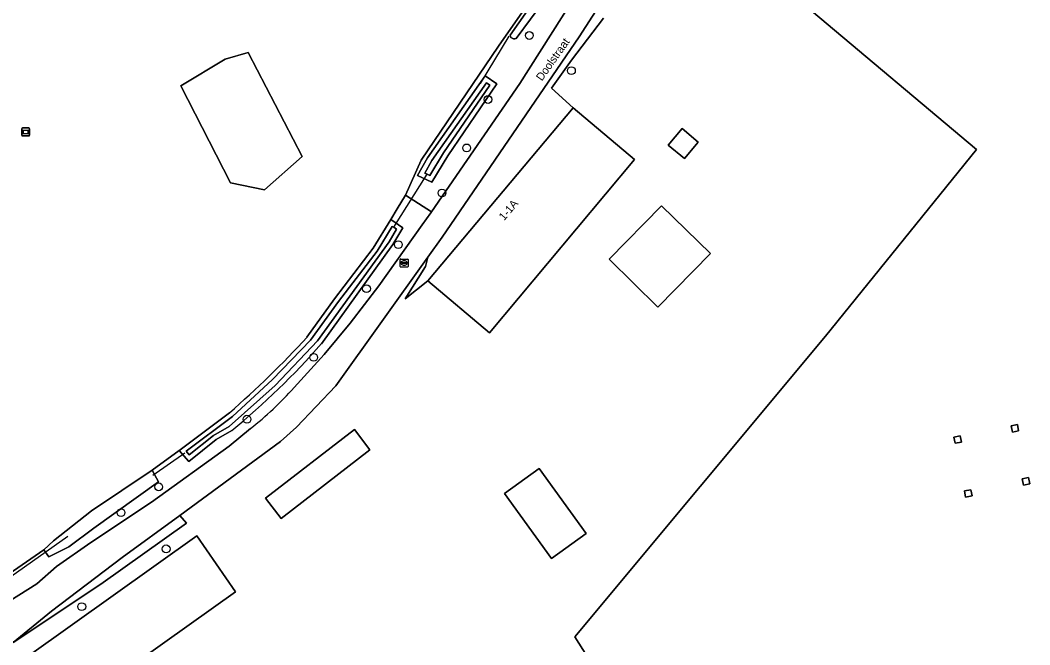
# Model space of a CAD drawing. Extents: x 164494 to 166241, y 382475 to 384495.
# Drawn here: x 165148.9 to 165275, y 383054.9 to 383132.9 of the extents above; entities that cross this region are included whole.
import ezdxf

# ---------------------------------------------------------------- set-up
doc = ezdxf.new("R2010")
doc.units = 0
for name, color, linetype in [('IMGEO_Boom', 7, 'Continuous'), ('IMGEO_Bouwland', 7, 'Continuous'), ('IMGEO_Duiker', 7, 'Continuous'), ('IMGEO_Erf', 7, 'Continuous'), ('IMGEO_Grasland_overig', 7, 'Continuous'), ('IMGEO_Groenvoorziening', 7, 'Continuous'), ('IMGEO_Hek', 7, 'Continuous'), ('IMGEO_Hoogspanningsmast', 7, 'Continuous'), ('IMGEO_Loofbos', 7, 'Continuous'), ('IMGEO_Oever', 7, 'Continuous'), ('IMGEO_Openbare_ruimte_label', 7, 'Continuous'), ('IMGEO_Pand', 7, 'Continuous'), ('IMGEO_Pand_nummerreeks', 7, 'Continuous'), ('IMGEO_Rijbaan_lokaal_halfverhard', 7, 'Continuous'), ('IMGEO_Rioolput', 7, 'Continuous'), ('IMGEO_Verklikker', 7, 'Continuous'), ('IMGEO_Waterloop', 7, 'Continuous')]:
    doc.layers.add(name, color=color, linetype=linetype)

msp = doc.modelspace()

# ---------------------------------------------------------------- linework, layer by layer
at = {"layer": 'IMGEO_Boom'}
for centre in [(165212.48, 383130.99), (165217.73, 383126.59), (165207.31, 383122.99), (165204.64, 383116.94), (165201.56, 383111.31), (165196.1, 383104.86), (165192.13, 383099.35), (165185.53, 383090.77), (165177.19, 383083.04), (165166.16, 383074.59), (165161.46, 383071.37), (165167.09, 383066.84), (165156.55, 383059.63)]:
    msp.add_circle(centre, 0.489, dxfattribs=at)
at = {"layer": 'IMGEO_Bouwland'}
for points in [[(165074.12, 383155.42), (165090.98, 383126.27), (165109.32, 383102.17), (165116.19, 383099.11), (165122.51, 383097.15), (165123.71, 383095.2), (165123.72, 383093.89), (165120.24, 383087.21), (165137.05, 383064.06), (165140.6, 383063.91), (165142.91, 383065.45), (165147.5, 383063.74), (165151.82, 383066.74), (165153, 383067.83), (165157.78, 383071.58), (165165.33, 383076.66), (165168.73, 383079.13), (165168.86, 383079.22), (165175, 383083.84)], [(165184.69, 383093.31), (165188.14, 383098.1), (165192.97, 383104.4), (165195.15, 383107.98), (165195.96, 383109.31), (165197, 383111.02), (165198.96, 383115.4), (165208.62, 383129.64), (165221.63, 383148.27)], [(165247.72, 383134.08), (165268.36, 383116.74), (165249.48, 383093.43), (165218.15, 383055.85), (165223.66, 383047.14)]]:
    msp.add_lwpolyline(points, dxfattribs=at)
for points in [[(165177.36, 383128.85), (165184.08, 383115.87), (165179.39, 383111.69), (165175.14, 383112.58), (165168.94, 383124.68), (165174.45, 383128.05)], [(165273.45, 383082.38), (165273.6, 383081.59), (165272.83, 383081.42), (165272.68, 383082.22)], [(165266.31, 383080.98), (165266.46, 383080.19), (165265.68, 383080.04), (165265.52, 383080.82)], [(165274.84, 383075.77), (165275.01, 383074.98), (165274.22, 383074.82), (165274.06, 383075.6)], [(165267.62, 383074.24), (165267.79, 383073.47), (165266.99, 383073.31), (165266.83, 383074.08)]]:
    msp.add_lwpolyline(points, close=True, dxfattribs=at)
msp.add_arc((165091.58, 383178.94), 126.51, 311.2584, 317.3955, dxfattribs=at)
at = {"layer": 'IMGEO_Duiker'}
for points in [[(165209.93, 383130.92), (165206.34, 383125)], [(165195.55, 383107.03), (165199.72, 383113.65)], [(165165.42, 383076.05), (165169.45, 383078.84)], [(165147.67, 383063.4), (165154.79, 383068.45)]]:
    msp.add_lwpolyline(points, dxfattribs=at)
at = {"layer": 'IMGEO_Erf'}
for points in [[(165147.19, 383054.58), (165154.26, 383044.06), (165156.24, 383041.34), (165158.94, 383038.39), (165159.48, 383037.85), (165160.12, 383037.5), (165161.03, 383037.44), (165161.58, 383037.57), (165162.78, 383037.82), (165169.28, 383031.59), (165170.09, 383032.35), (165171.96, 383030.47), (165176.32, 383026.1), (165185, 383018.32), (165194.85, 383024.31), (165208.27, 383034.25), (165223.66, 383047.14), (165218.15, 383055.85), (165249.48, 383093.43), (165268.36, 383116.74), (165247.72, 383134.08)], [(165221.76, 383133.17), (165217.74, 383127.91), (165215.23, 383124.42), (165217.94, 383121.93), (165225.63, 383115.48), (165207.5, 383093.85), (165199.79, 383100.32), (165196.97, 383098.1), (165199.49, 383102.14), (165199.81, 383103.29), (165188.28, 383087.23), (165183.37, 383082.04), (165181.4, 383080.25), (165168.79, 383071.02), (165169.63, 383070.04), (165158.92, 383062.43), (165147.97, 383055.13)]]:
    msp.add_lwpolyline(points, dxfattribs=at)
for points in [[(165229.84, 383117.3), (165231.57, 383119.36), (165233.58, 383117.67), (165231.86, 383115.61)], [(165222.44, 383103.02), (165229, 383109.72), (165235.09, 383103.76), (165228.53, 383097.06)], [(165192.55, 383079.23), (165181.45, 383070.63), (165179.49, 383073.16), (165190.61, 383081.75)], [(165213.7, 383076.89), (165219.57, 383068.78), (165215.23, 383065.65), (165209.36, 383073.75)], [(165175.75, 383061.48), (165157.81, 383048.67), (165156.81, 383050.14), (165153.69, 383047.91), (165150.01, 383053.56), (165170.91, 383068.49)]]:
    msp.add_lwpolyline(points, close=True, dxfattribs=at)
at = {"layer": 'IMGEO_Grasland_overig'}
for points in [[(165226.93, 383152.39), (165210.82, 383130.6), (165210.68, 383130.59), (165210.5, 383130.59), (165210.4, 383130.6), (165210.24, 383130.69), (165210.18, 383130.75), (165210.13, 383130.88), (165210.09, 383131.01), (165218.46, 383142.98)], [(165221.63, 383148.27), (165208.62, 383129.64), (165198.96, 383115.4), (165197, 383111.02), (165200.23, 383108.95), (165211.27, 383124.97), (165221.98, 383141.91)], [(165226.21, 383142.5), (165218.7, 383130.81), (165201.6, 383105.79), (165199.81, 383103.29), (165199.49, 383102.14), (165196.97, 383098.1), (165199.79, 383100.32), (165217.94, 383121.93), (165215.23, 383124.42), (165217.74, 383127.91), (165221.76, 383133.17)], [(165175.31, 383081.64), (165173.36, 383080.5), (165169.91, 383077.78), (165168.73, 383079.13), (165165.33, 383076.66), (165166.13, 383075.22), (165158.05, 383069.44), (165154.94, 383067.08), (165152.43, 383065.87), (165151.82, 383066.74), (165147.5, 383063.74), (165142.91, 383065.45), (165140.6, 383063.91), (165137.05, 383064.06), (165120.24, 383087.21), (165123.72, 383093.89), (165123.71, 383095.2), (165122.51, 383097.15), (165116.19, 383099.11), (165109.32, 383102.17), (165090.98, 383126.27)], [(165183.08, 383087), (165186.84, 383091.11), (165190.1, 383095.04), (165193.65, 383099.72), (165199.07, 383107.32), (165200.16, 383108.84), (165200.23, 383108.95), (165197, 383111.02), (165195.96, 383109.31), (165195.15, 383107.98), (165196.66, 383106.95), (165195.43, 383104.86), (165186.49, 383092.48)], [(165138.95, 383055.65), (165138.65, 383055.4), (165139.68, 383055.19), (165145.27, 383058.94), (165150.95, 383062.46), (165153.38, 383064.63), (165157.7, 383067.66), (165165.26, 383072.66), (165174.96, 383079.68), (165177.63, 383081.87)]]:
    msp.add_lwpolyline(points, dxfattribs=at)
msp.add_lwpolyline([(165206.95, 383125.96), (165208.43, 383124.96), (165202.29, 383115.96), (165200.29, 383112.66), (165198.52, 383113.49), (165199.74, 383115.69)], close=True, dxfattribs=at)
for centre, radius, start, end in [((165116.7, 383153.32), 92.59, 309.2748, 318.9253), ((165151.38, 383115.19), 42.42, 308.2249, 318.3405)]:
    msp.add_arc(centre, radius, start, end, dxfattribs=at)
at = {"layer": 'IMGEO_Groenvoorziening'}
msp.add_lwpolyline([(165152.79, 383059.07), (165147.97, 383055.13), (165158.92, 383062.43), (165169.63, 383070.04), (165168.79, 383071.02), (165161.61, 383065.76)], close=True, dxfattribs=at)
at = {"layer": 'IMGEO_Hek'}
msp.add_lwpolyline([(165249.48, 383093.43), (165268.36, 383116.74), (165248.56, 383133.37)], dxfattribs=at)
at = {"layer": 'IMGEO_Hoogspanningsmast'}
for points in [[(165273.6, 383081.59), (165273.45, 383082.38), (165272.68, 383082.22), (165272.83, 383081.42)], [(165265.68, 383080.04), (165266.46, 383080.19), (165266.31, 383080.98), (165265.52, 383080.82)], [(165274.84, 383075.77), (165274.06, 383075.6), (165274.22, 383074.82), (165275.01, 383074.98)], [(165266.83, 383074.08), (165266.99, 383073.31), (165267.79, 383073.47), (165267.62, 383074.24)]]:
    msp.add_lwpolyline(points, close=True, dxfattribs=at)
at = {"layer": 'IMGEO_Loofbos'}
msp.add_lwpolyline([(165184.08, 383115.87), (165177.36, 383128.85), (165174.45, 383128.05), (165168.94, 383124.68), (165175.14, 383112.58), (165179.39, 383111.69)], close=True, dxfattribs=at)
at = {"layer": 'IMGEO_Oever'}
for points in [[(165208.43, 383124.96), (165206.95, 383125.96), (165199.74, 383115.69), (165198.52, 383113.49), (165200.29, 383112.66), (165202.29, 383115.96)], [(165200.29, 383115.35), (165207.11, 383125.07), (165207.52, 383124.79), (165201.75, 383116.31), (165200.04, 383113.5), (165199.72, 383113.65), (165199.42, 383113.79)], [(165194.94, 383105.21), (165186.02, 383092.85), (165180.72, 383087.25), (165174.96, 383082.12), (165173.02, 383080.99), (165169.99, 383078.6), (165169.6, 383079.04), (165175.38, 383083.38), (165180.39, 383088.02), (165185.15, 383092.92), (165188.61, 383097.75), (165193.46, 383104.06), (165195.33, 383107.13), (165195.55, 383107.03), (165195.86, 383106.77)]]:
    msp.add_lwpolyline(points, close=True, dxfattribs=at)
for points in [[(165186.49, 383092.48), (165195.43, 383104.86), (165196.66, 383106.95), (165195.15, 383107.98), (165192.97, 383104.4), (165188.14, 383098.1), (165184.69, 383093.31)], [(165175, 383083.84), (165168.86, 383079.22), (165168.73, 383079.13), (165169.91, 383077.78), (165173.36, 383080.5), (165175.31, 383081.64)]]:
    msp.add_lwpolyline(points, dxfattribs=at)
for centre, radius, start, end in [((165091.58, 383178.94), 126.51, 311.2584, 317.3955), ((165116.7, 383153.32), 92.59, 309.2748, 318.9253)]:
    msp.add_arc(centre, radius, start, end, dxfattribs=at)
at = {"layer": 'IMGEO_Pand'}
for points in [[(165225.63, 383115.48), (165217.94, 383121.93), (165199.79, 383100.32), (165207.5, 383093.85)], [(165233.58, 383117.67), (165231.57, 383119.36), (165229.84, 383117.3), (165231.86, 383115.61)], [(165235.09, 383103.76), (165229, 383109.72), (165222.44, 383103.02), (165228.53, 383097.06)], [(165192.55, 383079.23), (165190.61, 383081.75), (165179.49, 383073.16), (165181.45, 383070.63)], [(165219.57, 383068.78), (165213.7, 383076.89), (165209.36, 383073.75), (165215.23, 383065.65)], [(165153.69, 383047.91), (165156.81, 383050.14), (165157.81, 383048.67), (165175.75, 383061.48), (165170.91, 383068.49), (165150.01, 383053.56)]]:
    msp.add_lwpolyline(points, close=True, dxfattribs=at)
at = {"layer": 'IMGEO_Rijbaan_lokaal_halfverhard'}
for points in [[(165177.63, 383081.87), (165174.96, 383079.68), (165165.26, 383072.66), (165157.7, 383067.66), (165153.38, 383064.63), (165150.95, 383062.46), (165145.27, 383058.94), (165147.97, 383055.13), (165152.79, 383059.07), (165161.61, 383065.76), (165168.79, 383071.02), (165181.4, 383080.25), (165183.37, 383082.04), (165188.28, 383087.23), (165199.81, 383103.29), (165201.6, 383105.79), (165218.7, 383130.81), (165226.21, 383142.5), (165232.13, 383150.82)], [(165221.98, 383141.91), (165211.27, 383124.97), (165200.23, 383108.95), (165200.16, 383108.84), (165199.07, 383107.32), (165193.65, 383099.72), (165190.1, 383095.04), (165186.84, 383091.11), (165183.08, 383087)]]:
    msp.add_lwpolyline(points, dxfattribs=at)
msp.add_arc((165151.38, 383115.19), 42.42, 308.2249, 318.3405, dxfattribs=at)
at = {"layer": 'IMGEO_Rioolput'}
for p, q in [((165196.33, 383102.14), (165196.33, 383102.99)), ((165196.4, 383103.06), (165197.25, 383103.06)), ((165196.81, 383102.84), (165196.84, 383102.84)), ((165197.33, 383102.99), (165197.33, 383102.14)), ((165197.25, 383102.06), (165196.4, 383102.06)), ((165196.58, 383102.56), (165196.58, 383102.57)), ((165197.02, 383102.52), (165196.62, 383102.52)), ((165196.63, 383102.61), (165197.03, 383102.61)), ((165196.84, 383102.28), (165196.81, 383102.28)), ((165197.07, 383102.57), (165197.07, 383102.56))]:
    msp.add_line(p, q, dxfattribs=at)
for points in [[(165196.33, 383102.14), (165196.33, 383102.99)], [(165196.4, 383103.06), (165197.25, 383103.06)], [(165197.33, 383102.99), (165197.33, 383102.14)], [(165197.25, 383102.06), (165196.4, 383102.06)]]:
    msp.add_lwpolyline(points, dxfattribs=at)
for centre, radius, start, end in [((165196.4, 383102.99), 0.0765, 91.552, 178.448), ((165196.4, 383102.99), 0.0765, 91.552, 178.448), ((165197.25, 383102.99), 0.0765, 1.552, 88.448), ((165197.25, 383102.99), 0.0765, 1.552, 88.448), ((165196.4, 383102.14), 0.0765, 181.552, 268.448), ((165196.4, 383102.14), 0.0765, 181.552, 268.448), ((165196.63, 383102.57), 0.0403, 85.8775, 175.7526), ((165196.62, 383102.56), 0.0366, 178.938, 274.7102), ((165197.03, 383102.56), 0.043, 264.8664, 352.4533), ((165197.03, 383102.57), 0.0386, 1.7309, 96.639), ((165197.25, 383102.14), 0.0765, 271.552, 358.448), ((165197.25, 383102.14), 0.0765, 271.552, 358.448)]:
    msp.add_arc(centre, radius, start, end, dxfattribs=at)
for centre, major_axis, ratio, start_param, end_param in [((165196.81, 383102.56), (-0.387, 0.002), 0.722429, 4.712389, 7.853982), ((165196.84, 383102.56), (-0.39, 0.002), 0.717154, 1.570796, 4.712389)]:
    msp.add_ellipse(centre, major_axis=major_axis, ratio=ratio, start_param=start_param, end_param=end_param, dxfattribs=at)
at = {"layer": 'IMGEO_Verklikker'}
for p, q in [((165149.05, 383118.53), (165149.05, 383119.33)), ((165149.05, 383119.33), (165149.05, 383118.53)), ((165149.15, 383119.43), (165149.94, 383119.43)), ((165149.94, 383119.43), (165149.15, 383119.43)), ((165150.04, 383119.33), (165150.04, 383118.53)), ((165150.04, 383118.53), (165150.04, 383119.33)), ((165149.94, 383118.43), (165149.15, 383118.43)), ((165149.15, 383118.43), (165149.94, 383118.43))]:
    msp.add_line(p, q, dxfattribs=at)
for points in [[(165149.15, 383119.16), (165149.94, 383119.16), (165149.94, 383118.7), (165149.15, 383118.7), (165149.15, 383119.16)], [(165149.22, 383119.1), (165149.22, 383118.76), (165149.87, 383118.76), (165149.87, 383119.1), (165149.22, 383119.1)]]:
    msp.add_lwpolyline(points, dxfattribs=at)
for centre, start, end in [((165149.15, 383119.33), 90, 180), ((165149.15, 383119.33), 90, 180), ((165149.94, 383119.33), 0, 90), ((165149.94, 383119.33), 360, 90), ((165149.15, 383118.53), 180, 270), ((165149.15, 383118.53), 180, 270), ((165149.94, 383118.53), 270, 0), ((165149.94, 383118.53), 270, 0)]:
    msp.add_arc(centre, 0.1, start, end, dxfattribs=at)
at = {"layer": 'IMGEO_Waterloop'}
msp.add_lwpolyline([(165218.46, 383142.98), (165210.09, 383131.01), (165210.13, 383130.88), (165210.18, 383130.75), (165210.24, 383130.69), (165210.4, 383130.6), (165210.5, 383130.59), (165210.68, 383130.59), (165210.82, 383130.6), (165226.93, 383152.39)], dxfattribs=at)
for points in [[(165200.29, 383115.35), (165199.42, 383113.79), (165199.72, 383113.65), (165200.04, 383113.5), (165201.75, 383116.31), (165207.52, 383124.79), (165207.11, 383125.07)], [(165186.02, 383092.85), (165194.94, 383105.21), (165195.86, 383106.77), (165195.55, 383107.03), (165195.33, 383107.13), (165193.46, 383104.06), (165188.61, 383097.75), (165185.15, 383092.92), (165180.39, 383088.02), (165175.38, 383083.38), (165169.6, 383079.04), (165169.99, 383078.6), (165173.02, 383080.99), (165174.96, 383082.12), (165180.72, 383087.25)], [(165157.78, 383071.58), (165153, 383067.83), (165151.82, 383066.74), (165152.43, 383065.87), (165154.94, 383067.08), (165158.05, 383069.44), (165166.13, 383075.22), (165165.33, 383076.66)]]:
    msp.add_lwpolyline(points, close=True, dxfattribs=at)

# ---------------------------------------------------------------- texts
at = {"layer": 'IMGEO_Openbare_ruimte_label'}
msp.add_text('Doolstraat', height=1, rotation=54.6089, dxfattribs=at).set_placement((165214.04, 383125.23))
at = {"layer": 'IMGEO_Pand_nummerreeks'}
msp.add_text('1-1A', height=1, rotation=49.9676, dxfattribs=at).set_placement((165209.33, 383107.79))

doc.saveas('drawing.dxf')
